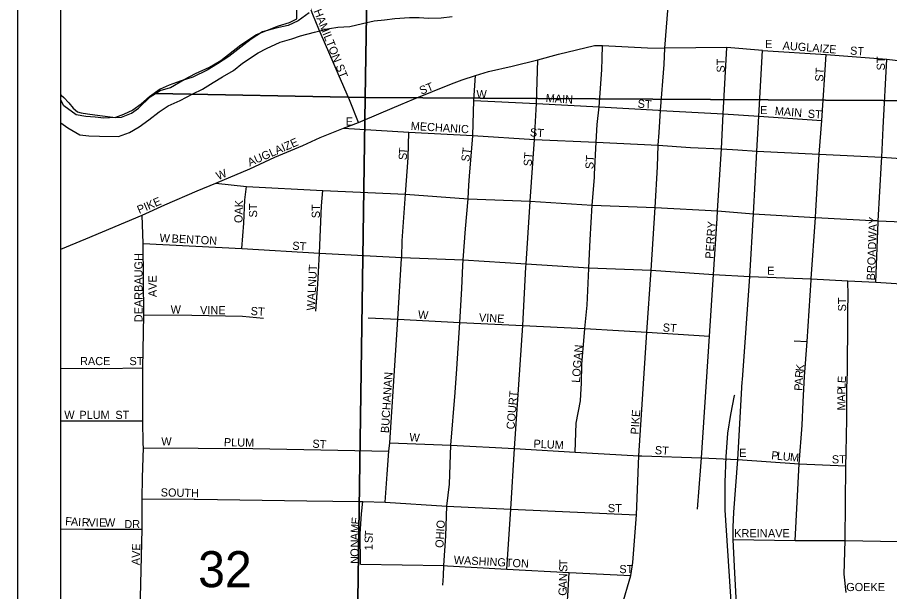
# Model space of a CAD drawing. Extents: x -784 to 1375, y -225 to 440.
# Drawn here: x 65.09 to 105.18, y 334.55 to 360.96 of the extents above; entities that cross this region are included whole.
import ezdxf

# ---------------------------------------------------------------- set-up
doc = ezdxf.new("R2010")
doc.units = 0
for name, color, linetype in [('GM_X_City_Street', 7, 'Continuous'), ('GM_X_City_Street_Text', 7, 'Continuous'), ('GM_X_Major_River', 7, 'Continuous'), ('GM_X_Rail_Line', 7, 'Continuous'), ('GM_X_Section', 7, 'Continuous'), ('GM_X_Section_Text', 7, 'Continuous'), ('GM_X_State_Route', 7, 'Continuous'), ('SH_Data', 7, 'Continuous'), ('SH_Text', 7, 'Continuous')]:
    doc.layers.add(name, color=color, linetype=linetype)

msp = doc.modelspace()

# ---------------------------------------------------------------- linework, layer by layer
at = {"layer": 'GM_X_City_Street'}
msp.add_line((67.088, 342.406), (70.846, 342.406), dxfattribs=at)
for points in [[(80.763, 356.122), (80.35, 357.171), (79.837, 358.365), (79.646, 358.801), (79.202, 359.826), (78.949, 360.416), (78.674, 361.097), (78.505, 361.533), (78.268, 362.069), (78.228, 362.302)], [(74.213, 353.337), (75.77, 354.001), (76.913, 354.528), (78.211, 355.07), (79.011, 355.437), (80.071, 355.87), (80.763, 356.122), (81.812, 356.574), (82.715, 356.949), (83.296, 357.194), (85.037, 357.909), (85.535, 358.086), (86.147, 358.292), (86.744, 358.468), (87.823, 358.721), (89.002, 359.004), (89.958, 359.272), (91.61, 359.673), (91.986, 359.673), (94.045, 359.567), (94.853, 359.554)], [(91.618, 353.752), (91.692, 355.228), (91.741, 356.036), (91.828, 356.85), (91.947, 358.552), (91.961, 359.075), (91.986, 359.673)], [(91.68, 329.482), (92.456, 332.472), (93.284, 335.289), (93.372, 335.892), (93.537, 338.077), (93.645, 340.796), (94.021, 346.476), (94.217, 349.327), (94.405, 352.212), (94.511, 354.091), (94.544, 355.08), (94.584, 355.669), (94.642, 356.682), (94.812, 358.8), (94.853, 359.554)], [(97.247, 351.713), (97.27, 352.058), (97.444, 354.917), (97.526, 356.527), (97.698, 359.583)], [(99.332, 359.444), (102.266, 359.248), (105.044, 359.044), (105.812, 358.954), (107.272, 358.878), (108.266, 358.837)], [(101.785, 352.064), (101.947, 354.664), (102.07, 356.223), (102.266, 359.248)], [(88.636, 352.254), (88.652, 352.514), (88.849, 355.346), (88.948, 356.999), (89.002, 359.004)], [(104.888, 355.886), (105.044, 359.044)], [(86.014, 355.507), (86.015, 355.53), (86.071, 357.137), (86.147, 358.292)], [(86.071, 357.137), (88.948, 356.999), (91.828, 356.85), (94.549, 356.688)], [(94.549, 356.688), (94.642, 356.682), (97.247, 356.542)], [(97.247, 356.542), (97.526, 356.527), (99.173, 356.42)], [(99.173, 356.42), (102.07, 356.223)], [(80.071, 355.87), (83.086, 355.68), (86.015, 355.53), (88.849, 355.346), (91.692, 355.228), (94.544, 355.08), (96.031, 354.974), (97.444, 354.917), (98.204, 354.868), (99.079, 354.811), (101.947, 354.664), (104.821, 354.525), (108.096, 354.301), (110.837, 354.198), (113.207, 354.051), (115.757, 353.865)], [(82.749, 349.877), (82.751, 349.909), (82.779, 350.686), (82.925, 352.828), (83.048, 354.496), (83.086, 355.68)], [(104.809, 354.307), (104.821, 354.525), (104.888, 355.886)], [(85.568, 349.549), (85.579, 349.81), (85.686, 351.24), (85.807, 352.621), (85.841, 353.249), (85.872, 353.654), (86.014, 355.507)], [(104.651, 351.546), (104.653, 351.611), (104.809, 354.307)], [(91.348, 349.41), (91.348, 349.434), (91.414, 350.725), (91.512, 352.326), (91.61, 353.593), (91.618, 353.752)], [(67.088, 350.305), (68.231, 350.782), (70.818, 351.861), (71.864, 352.344), (73.352, 352.979), (74.213, 353.337)], [(74.213, 353.337), (75.624, 353.187), (79.122, 353.004), (82.925, 352.828), (85.807, 352.621), (88.652, 352.514), (91.512, 352.326), (94.405, 352.212)], [(75.396, 350.324), (75.501, 351.499), (75.541, 352.565), (75.624, 353.187)], [(78.912, 348.964), (78.929, 349.254), (78.969, 350.115), (79.065, 352.295), (79.122, 353.004)], [(88.464, 349.475), (88.472, 349.63), (88.636, 352.254)], [(94.405, 352.212), (97.27, 352.058), (98.919, 351.93)], [(101.57, 348.871), (101.574, 348.935), (101.765, 351.752), (101.785, 352.064)], [(70.894, 347.274), (70.861, 350.563), (70.818, 351.861)], [(96.505, 340.307), (96.537, 340.698), (96.905, 346.304), (97.077, 349.14), (97.247, 351.713)], [(104.551, 348.781), (104.651, 351.546)], [(70.861, 350.563), (75.396, 350.324), (78.969, 350.115), (82.751, 349.909), (85.579, 349.81), (88.472, 349.63), (91.348, 349.434), (94.217, 349.327), (97.077, 349.14), (98.761, 349.05)], [(81.999, 338.664), (82.087, 339.952), (82.159, 341.014), (82.2, 341.384), (82.572, 347.072), (82.749, 349.877)], [(84.638, 334.842), (84.67, 335.277), (84.692, 335.748), (84.775, 337.119), (84.831, 338.479), (84.952, 339.485), (85.016, 341.287), (85.204, 343.705), (85.285, 344.8), (85.424, 346.933), (85.522, 348.486), (85.568, 349.549)], [(87.583, 335.582), (87.768, 338.334), (87.941, 341.123), (88.325, 346.786), (88.464, 349.475)], [(91.143, 346.268), (91.177, 346.647), (91.283, 347.718), (91.348, 349.41)], [(78.8, 347.451), (78.896, 348.69), (78.912, 348.964)], [(98.761, 349.05), (101.574, 348.935), (103.26, 348.845), (104.551, 348.781), (107.839, 348.564), (108.231, 348.541), (110.555, 348.456), (115.743, 348.168), (118.054, 348.079), (120.479, 347.915), (123.155, 347.733), (125.081, 347.668), (125.889, 347.601), (128.722, 347.515), (129.501, 347.466)], [(101.21, 343.282), (101.261, 344.437), (101.389, 346.05), (101.57, 348.871)], [(103.257, 347.294), (103.254, 347.484), (103.267, 348.162), (103.26, 348.845)], [(70.873, 341.365), (70.846, 342.406), (70.846, 344.836), (70.894, 347.274)], [(70.894, 347.274), (73.103, 347.266), (75.437, 347.21), (76.394, 347.129)], [(103.198, 341.863), (103.212, 342.323), (103.219, 343.913), (103.248, 344.648), (103.26, 347.114), (103.257, 347.294)], [(81.216, 347.146), (82.233, 347.091)], [(82.233, 347.091), (82.572, 347.072), (85.424, 346.933), (88.325, 346.786), (91.177, 346.647), (92.712, 346.555)], [(92.712, 346.555), (94.021, 346.476), (96.905, 346.304)], [(90.984, 343.609), (91.022, 344.139), (91.03, 345.013), (91.143, 346.268)], [(100.795, 346.082), (101.389, 346.05)], [(67.088, 344.83), (69.003, 344.812), (70.846, 344.836)], [(90.72, 340.964), (90.768, 342.292), (90.964, 343.33), (90.984, 343.609)], [(100.836, 336.893), (101.019, 340.429), (101.162, 342.208), (101.21, 343.282)], [(103.18, 334.498), (103.091, 335.341), (103.129, 336.893), (103.161, 340.33), (103.18, 340.924), (103.193, 341.722), (103.198, 341.863)], [(70.841, 339.789), (70.878, 341.159), (70.873, 341.365)], [(70.878, 341.159), (75.907, 341.135), (82.159, 341.014)], [(82.2, 341.384), (85.016, 341.287), (87.941, 341.123), (90.72, 340.964), (93.645, 340.796), (93.795, 340.791)], [(93.795, 340.791), (96.537, 340.698), (98.196, 340.627)], [(98.196, 340.627), (101.019, 340.429), (103.161, 340.33)], [(96.345, 338.343), (96.505, 340.307)], [(70.822, 337.425), (70.814, 338.811), (70.841, 339.789)], [(70.814, 338.811), (73.208, 338.794)], [(73.208, 338.794), (73.263, 338.794), (78.393, 338.729)], [(78.393, 338.729), (80.787, 338.699)], [(80.787, 338.699), (80.969, 338.697), (81.999, 338.664), (84.831, 338.479), (87.768, 338.334), (93.537, 338.077)], [(80.856, 335.816), (80.848, 337.2), (80.906, 338.122), (80.969, 338.697)], [(67.088, 337.437), (68.191, 337.425), (70.822, 337.425)], [(70.541, 326.113), (70.822, 337.425)], [(97.987, 336.937), (100.836, 336.893), (103.129, 336.893), (105.576, 336.855), (108.042, 336.784), (109.511, 336.874)], [(80.856, 335.816), (84.692, 335.748), (84.859, 335.739)], [(84.859, 335.739), (87.583, 335.582), (90.455, 335.426), (93.284, 335.289)], [(90.262, 332.585), (90.311, 333.189), (90.403, 334.593), (90.455, 335.426)]]:
    msp.add_lwpolyline(points, dxfattribs=at)
at = {"layer": 'GM_X_Major_River'}
for points in [[(78.503, 361.174), (77.987, 360.805), (77.534, 360.586), (76.961, 360.474), (76.358, 360.302), (75.828, 359.964), (75.358, 359.594), (74.811, 359.166), (74.281, 358.828), (73.811, 358.534), (73.146, 358.213), (72.573, 358.025), (72.06, 357.852), (71.652, 357.662), (71.166, 357.308), (70.771, 356.968), (70.392, 356.688), (69.969, 356.499), (69.591, 356.353), (69.065, 356.331), (68.66, 356.366), (68.225, 356.402), (67.79, 356.484), (67.225, 356.897), (67.088, 357.156)], [(67.088, 356.116), (67.407, 355.888), (67.958, 355.565), (68.363, 355.514), (68.859, 355.492), (69.73, 355.48), (70.243, 355.668), (70.682, 355.933), (71.122, 356.257), (71.608, 356.611), (72.017, 356.891), (72.561, 357.139), (73.151, 357.446), (73.589, 357.666), (74.089, 357.974), (74.513, 358.224), (75.013, 358.517), (75.438, 358.857), (76.15, 359.328), (76.543, 359.533), (77.163, 359.825), (77.706, 359.983), (78.098, 360.113), (78.747, 360.284), (79.44, 360.455), (79.816, 360.51), (80.372, 360.547), (80.945, 360.674), (81.487, 360.802), (81.954, 360.856), (82.435, 360.909)], [(82.435, 360.909), (83.112, 360.96), (83.547, 360.954), (83.983, 360.933), (84.569, 360.94), (85.065, 361.008)]]:
    msp.add_lwpolyline(points, dxfattribs=at)
at = {"layer": 'GM_X_Rail_Line'}
for points in [[(98.775, 319.233), (98.355, 327.064), (97.622, 338.297), (97.613, 339.578), (97.673, 340.741), (97.75, 341.835), (97.878, 342.698), (98.049, 343.561)], [(98.049, 343.561), (98.058, 343.601)]]:
    msp.add_lwpolyline(points, dxfattribs=at)
at = {"layer": 'GM_X_Section'}
for points in [[(67.088, 397.216), (81.709, 397.114), (81.068, 357.283), (71.441, 357.464), (71.653, 357.594), (72.121, 357.736), (72.758, 358.099), (73.273, 358.374), (73.924, 358.677), (74.439, 358.982), (75.353, 359.701), (76.082, 360.182), (77.094, 360.568), (77.592, 360.724), (77.925, 360.897), (78.122, 386.365), (67.088, 386.554)], [(121.281, 389.014), (120.755, 357.05), (81.068, 357.283), (81.709, 397.114), (86.63, 397.087)], [(67.088, 357.38), (67.104, 357.38), (67.222, 357.273), (67.443, 357.028), (67.648, 356.785), (67.855, 356.616), (68.019, 356.568), (68.303, 356.532), (68.872, 356.446), (69.59, 356.358), (69.875, 356.368), (70.329, 356.554), (70.648, 356.788), (71.183, 357.303), (71.441, 357.464), (81.068, 357.283), (80.486, 317.362), (80.366, 317.364), (67.088, 317.379)], [(67.088, 357.409), (67.104, 357.38), (67.088, 357.38)]]:
    msp.add_lwpolyline(points, dxfattribs=at)
msp.add_lwpolyline([(81.068, 357.283), (120.755, 357.05), (120.146, 317.31), (119.981, 317.313), (80.486, 317.362)], close=True, dxfattribs=at)
at = {"layer": 'GM_X_State_Route'}
for points in [[(94.853, 359.554), (95.026, 361.871), (94.969, 362.762), (94.813, 363.473), (93.612, 365.05), (92.503, 366.349)], [(98.919, 351.93), (99.079, 354.811), (99.173, 356.42), (99.332, 359.444), (97.698, 359.583), (94.853, 359.554)], [(98.409, 344.193), (98.415, 344.284), (98.761, 349.05), (98.919, 351.93)], [(98.919, 351.93), (101.765, 351.752), (104.653, 351.611), (107.93, 351.458), (110.696, 351.324), (115.762, 351.055), (120.48, 350.682), (120.49, 351.099)], [(98.221, 332.97), (98.159, 333.692), (98.045, 335.698), (97.987, 336.937), (97.993, 337.513), (98.025, 338.203), (98.196, 340.627), (98.409, 344.193)]]:
    msp.add_lwpolyline(points, dxfattribs=at)
at = {"layer": 'SH_Data'}
msp.add_line((65.088, 421.485), (65.088, 281.485), dxfattribs=at)
at = {"layer": 'SH_Text'}
msp.add_lwpolyline([(67.088, 419.485), (203.088, 419.485), (203.088, 283.485), (67.088, 283.485)], close=True, dxfattribs=at)

# ---------------------------------------------------------------- texts
at = {"layer": 'GM_X_City_Street_Text'}
for s, rotation, p in [('HAMILTON ST', 291.6341, (78.696, 361.259)), ('E', 0, (99.455, 359.551)), ('AUGLAIZE', 355.7133, (100.253, 359.484)), ('ST', 356.4254, (103.354, 359.254)), ('ST', 90, (97.603, 358.424)), ('ST', 90, (104.962, 358.523)), ('ST', 86.4118, (102.124, 357.999)), ('ST', 21.8039, (83.655, 357.401)), ('W', 0, (86.189, 357.241)), ('MAIN', 356.3452, (89.362, 357.075)), ('ST', 356.4254, (93.586, 356.811)), ('E', 0, (99.224, 356.514)), ('MAIN', 355.3674, (99.89, 356.481)), ('ST', 356.4254, (101.407, 356.349)), ('E', 0, (80.183, 355.986)), ('MECHANIC', 356.5954, (83.158, 355.788)), ('ST', 356.4262, (88.636, 355.491)), ('AUGLAIZE', 23.6285, (75.765, 354.1)), ('T', 86.0623, (82.995, 354.655)), ('ST', 82.8649, (85.855, 354.308)), ('S', 87.4036, (82.984, 354.393)), ('ST', 86.4254, (88.726, 354.105)), ('ST', 86.4118, (91.564, 353.973)), ('W', 22.6224, (74.315, 353.473)), ('PIKE', 23.2005, (70.685, 351.921)), ('OAK', 88.0918, (75.427, 351.496)), ('ST', 90, (76.105, 351.758)), ('ST', 90, (78.991, 351.725)), ('PERRY', 86.183, (97.075, 349.849)), ('BROADWAY', 87.9059, (104.5, 348.857)), ('W', 355.6039, (71.609, 350.64)), ('BENTON', 356.9315, (72.168, 350.608)), ('ST', 356.4254, (77.713, 350.277)), ('DEARBAUGH', 90, (70.84, 346.94)), ('WALNUT', 87.1867, (78.76, 347.471)), ('E', 0, (99.554, 349.122)), ('AVE', 90, (71.485, 348.095)), ('ST', 90, (103.18, 347.435)), ('W', 0, (72.131, 347.34)), ('VINE', 0, (73.484, 347.307)), ('ST', 356.4262, (75.799, 347.274)), ('W', 355.6039, (83.489, 347.109)), ('VINE', 356.5338, (86.293, 346.977)), ('ST', 356.4254, (94.741, 346.515)), ('LOGAN', 85.3357, (90.937, 344.141)), ('RACE', 0, (67.966, 344.965)), ('ST', 0, (70.237, 344.965)), ('K', 83.3412, (101.226, 344.658)), ('BUCHANAN', 86.3777, (82.159, 341.83)), ('A', 86.8505, (101.18, 344.039)), ('R', 84.5528, (101.198, 344.364)), ('E', 86.6929, (103.16, 344.129)), ('P', 87.0748, (101.167, 343.775)), ('L', 87.622, (103.149, 343.867)), ('COURT', 85.1382, (87.934, 341.996)), ('A', 89.9703, (103.147, 343.277)), ('P', 89.5355, (103.147, 343.606)), ('M', 89.9636, (103.147, 342.881)), ('W', 0, (67.241, 342.49)), ('PLUM', 0, (67.935, 342.49)), ('ST', 0, (69.59, 342.49)), ('PIKE', 86.3038, (93.644, 341.763)), ('W', 0, (71.702, 341.269)), ('PLUM', 358.8284, (74.576, 341.236)), ('W', 355.6039, (83.093, 341.466)), ('ST', 356.4254, (78.637, 341.17)), ('PLUM', 357.066, (88.8, 341.17)), ('ST', 356.4262, (94.378, 340.873)), ('E', 0, (98.267, 340.741)), ('P', 354.197, (99.727, 340.641)), ('L', 354.197, (99.989, 340.615)), ('U', 354.1981, (100.252, 340.588)), ('M', 354.7034, (100.584, 340.554)), ('ST', 0, (102.524, 340.444)), ('SOUTH', 358.7554, (71.671, 338.926)), ('ST', 0, (92.228, 338.2)), ('F', 356.3368, (67.272, 337.605)), ('A', 356.3448, (67.536, 337.589)), ('E', 85.0208, (80.809, 337.624)), ('I', 356.3504, (67.865, 337.568)), ('R', 357.2372, (68.036, 337.557)), ('V', 359.5987, (68.35, 337.542)), ('I', 359.985, (68.682, 337.54)), ('E', 359.9956, (68.847, 337.54)), ('W', 359.9988, (69.111, 337.54)), ('DR', 0, (70.002, 337.465)), ('M', 85.625, (80.779, 337.231)), ('OHIO', 86.7251, (84.667, 336.549)), ('A', 88.9945, (80.773, 336.906)), ('T', 85.8988, (81.422, 337.033)), ('KREIN', 0, (98.036, 337.044)), ('AVE', 0, (99.587, 337.045)), ('N', 89.9703, (80.773, 336.578)), ('S', 89.235, (81.418, 336.775)), ('AVE', 88.0186, (70.708, 335.756)), ('O', 89.9703, (80.773, 336.149)), ('1', 89.9688, (81.418, 336.446)), ('N', 89.9563, (80.773, 335.819)), ('WASHINGTON', 356.9546, (85.137, 335.824)), ('T', 88.7128, (90.368, 335.712)), ('S', 88.7016, (90.362, 335.448)), ('ST', 0, (92.756, 335.395)), ('N', 88.7092, (90.352, 335.019)), ('A', 88.4502, (90.343, 334.687)), ('GOEKE', 0, (103.184, 334.57)), ('G', 86.4914, (90.322, 334.344))]:
    msp.add_text(s, height=0.375, rotation=rotation, dxfattribs=at).set_placement(p)
at = {"layer": 'GM_X_Section_Text'}
msp.add_text('32', height=1.6575, rotation=0, dxfattribs=at).set_placement((73.394, 334.749))

doc.saveas('drawing.dxf')
